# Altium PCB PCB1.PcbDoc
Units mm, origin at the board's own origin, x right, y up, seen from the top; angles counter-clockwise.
Board outline 12.57 x 10.41 mm, 2 copper layers (Top Layer, Bottom Layer); 7 components, 5 nets, 23 pads, 8 vias.
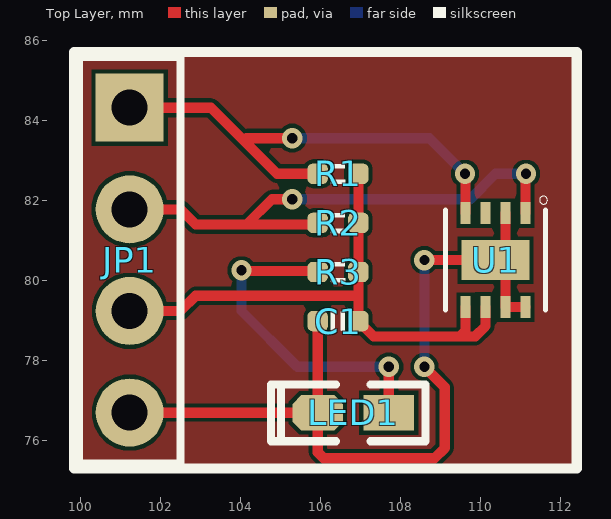
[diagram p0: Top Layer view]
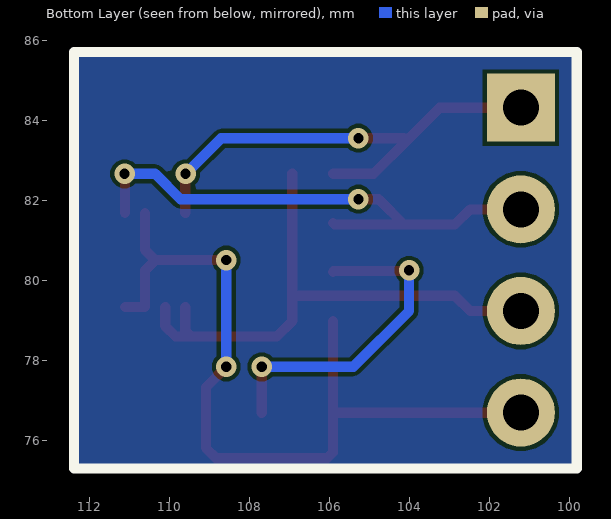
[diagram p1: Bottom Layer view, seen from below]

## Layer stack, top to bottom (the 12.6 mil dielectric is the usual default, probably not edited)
Top Solder: solder mask 0.0102, Solder Resist, Dk 3.5
Top Layer: signal copper 0.0356
Dielectric 1: dielectric 0.32, FR-4, Dk 4.8
Bottom Layer: signal copper 0.0356
Bottom Solder: solder mask 0.0102, Solder Resist, Dk 3.5

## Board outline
99.822,75.311 99.822,85.725 112.395,85.725 112.395,75.311

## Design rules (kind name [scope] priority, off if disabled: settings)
Clearance [All] p1: gap=0.102 ignorepadtopadclearanceinfootprint=FALSE except(0: Arc-Hole Track-Hole SMDPad-Hole THPad-Hole Via-Hole Fill-Hole Poly-Hole Region-Hole Text-Hole; 0.064: SMDPad-Via)
ComponentClearance [All] p1: gap=0 collisioncheckmode=3 verticalgap=0 showdistances=FALSE
DiffPairsRouting [All] p1: maxlimit=0.102 minlimit=0.102 mostfreqgap=0.102 toplayer_minwidth=0.102 toplayer_maxwidth=0.102 toplayer_prefwidth=0.102 bottomlayer_minwidth=0.102 bottomlayer_maxwidth=0.102 bottomlayer_prefwidth=0.102 maxuncoupledlength=12.7
FanoutControl Fanout_BGA [All] p1: bgadir=Out bgaviamode=Centered fanoutstyle=Auto fanoutdirection=Alternating viagrid=0.025 // Fanout_BGA (Default Rule)
HoleSize [All] p1: absolutevalues=TRUE maxlimit=254 minlimit=0.089 maxpercent=80.000 minpercent=20.000
MatchedLengths MatchedLengths_DIFF [InDifferentialPairClass('All Differential Pairs')] p1: tolerance=0.127 checknetsindiffpair=TRUE checkdiffpairvsdiffpair=FALSE checkxsignals=FALSE checkothers=FALSE
MatchedLengths MatchedLengths_DQS1 [InDifferentialPair('SDQS1')] p2: tolerance=0.127 checknetsindiffpair=TRUE checkdiffpairvsdiffpair=FALSE checkxsignals=FALSE checkothers=FALSE
MatchedLengths MatchedLengths_DQS0 [InDifferentialPair('SDQS0')] p3: tolerance=0.127 checknetsindiffpair=TRUE checkdiffpairvsdiffpair=FALSE checkxsignals=FALSE checkothers=FALSE
MatchedLengths MatchedLengths_SCK_CS [InNetClass('DDR_SCK_CS')] p4: tolerance=7.62 checknetsindiffpair=FALSE checkdiffpairvsdiffpair=TRUE checkxsignals=TRUE checkothers=TRUE
MatchedLengths MatchedLengths_SCK_DQS [InNetClass('DDR_SCK_DQS')] p5: tolerance=15.24 checknetsindiffpair=FALSE checkdiffpairvsdiffpair=TRUE checkxsignals=TRUE checkothers=TRUE
MatchedLengths MatchedLengths_CMD [InNetClass('DDR_CMD')] p6: tolerance=12.7 checknetsindiffpair=FALSE checkdiffpairvsdiffpair=TRUE checkxsignals=TRUE checkothers=TRUE
MatchedLengths MatchedLengths_DATAH [InNetClass('DDR_DATAH')] p7: tolerance=6.35 checknetsindiffpair=FALSE checkdiffpairvsdiffpair=TRUE checkxsignals=TRUE checkothers=TRUE
MatchedLengths MatchedLengths_DATAL [InNetClass('DDR_DATAL')] p8: tolerance=6.35 checknetsindiffpair=FALSE checkdiffpairvsdiffpair=TRUE checkxsignals=TRUE checkothers=TRUE
MatchedLengths MatchedLengths_SCK [InDifferentialPair('SCK')] p9: tolerance=0.127 checknetsindiffpair=TRUE checkdiffpairvsdiffpair=FALSE checkxsignals=FALSE checkothers=FALSE
MinimumSolderMaskSliver [All] p1 off: minsoldermaskwidth=0.051
PlaneClearance [All] p1: clearance=0.203
PlaneConnect [All] p1: planeconnectstyle=Direct reliefexpansion=0.508 reliefentries=4 reliefconductorwidth=0.254 reliefairgap=0.254
PolygonConnect PolygonConnect_VDD-5V [All vs IsNamedPolygon('VDD-5V_L01_P009')] p1: thpad.connectstyle=Direct thpad.reliefconductorwidth=0.254 thpad.reliefentries=4 thpad.polygonreliefangle="90 Angle" thpad.airgapwidth=0.254 smdpad.connectstyle=Relief smdpad.reliefconductorwidth=0.254 smdpad.reliefentries=4 smdpad.polygonreliefangle="90 Angle" smdpad.airgapwidth=0.254 via.connectstyle=Direct via.reliefconductorwidth=0.254 via.reliefentries=4 via.polygonreliefangle="90 Angle" via.airgapwidth=0.254
PolygonConnect [All] p2: connectstyle=Direct reliefconductorwidth=0.254 reliefentries=4 polygonreliefangle="90 Angle" airgapwidth=0.254
RoutingVias [All] p1: holewidth=0.203 width=0.406 viastyle="Through Hole" minholewidth=0.152 minwidth=0.305 maxholewidth=0.711 maxwidth=1.27
SilkToSilkClearance [All] p1: silktosilkclearance=0
SilkToSolderMaskClearance [IsPad] p1: minsilkscreentomaskgap=0 clearancetoexposedcopper=TRUE
SolderMaskExpansion [All] p1: expansion=0.076 istentingtop=FALSE
Width GND [(InNet('AGND') OR InNet('GND'))] p1: maxlimit=1.27 minlimit=0.102 preferedwidth=0.254
Width VCC [(InNet('VDD_SYS_3.3V') OR InNet('VDD_AV_3.3V') OR InNet('VDD_5V') OR InNet('VDD1V2-SYS') OR InNet('VDD1V1-EPHY') OR InNet('VDD-CPUX') OR InNet('VDD-CPUS') OR InNet('VDD-CPUFB') OR InNet('VCC-DRAM'))] p2: maxlimit=1.27 minlimit=0.102 preferedwidth=0.254
Width [All] p3: maxlimit=254 minlimit=0.102 preferedwidth=0.102
21 further rules are at their usual default settings.

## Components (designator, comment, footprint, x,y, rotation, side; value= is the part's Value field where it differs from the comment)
C1 "0.1uF" CAP_0402 106.426,78.994 r180 top value=0.1u
JP1 "HDR-1X4" HDR2.54-LI-4P 101.219,80.518 r270 top
LED1 "红色" LED0603_R 106.807,76.708 r180 top
R1 "10K" RES_0402 106.426,82.677 r0 top value=22R
R2 "10K" RES_0402 106.426,81.449 r0 top value=22R
R3 "10K" RES_0402 106.426,80.222 r0 top value=22R
U1 "SHT30-DIS" DFN250X250X100-9N 110.363,80.518 r270 top locked

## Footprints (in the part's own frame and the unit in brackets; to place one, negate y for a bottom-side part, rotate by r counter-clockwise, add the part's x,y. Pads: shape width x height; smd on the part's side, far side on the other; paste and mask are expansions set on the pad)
CAP_0402 [mil]
  rrect50% 20x20 smd: 1(-20,0) 2(20,0)
  silkscreen extent -7,-9 7,9, body extent -20,-10 20,10, height 20
DFN250X250X100-9N [mm]
  rect 0.55x0.25 smd: 1(-1.175,0.75) 2(-1.175,0.25) 3(-1.175,-0.25) 4(-1.175,-0.75) 5(1.175,-0.75) 6(1.175,-0.25) 7(1.175,0.25) 8(1.175,0.75)
  rect 1x1.7 smd: 9(0,0)
  silkscreen extent -1.6,-1.25 1.25,1.3, body extent -1.25,-1.25 1.25,1.25, height 0.9
HDR2.54-LI-4P [mm] "排针，4脚"
  rect 1.7x1.7 hole 0.9: 1(-3.81,0)
  round 1.7 hole 0.9: 2(-1.27,0) 3(1.27,0) 4(3.81,0)
  silkscreen extent -5.08,-1.27 5.08,1.27, body extent -5.08,-1.27 5.08,1.27, height 2.54
LED0603_R [mil] "红色0603LED"
  rect 50x35 smd: 1(-35,0.26)
  oct 50x35 smd: 2(35,0.26)
  silkscreen extent -71,-28 81,28, body extent -32,-16 31,16, height 18
RES_0402 [mil]
  rrect50% 20x20 smd: 1(-20,0) 2(20,0)
  silkscreen extent -6,-10 6,10, body extent -20,-10 20,10, height 14

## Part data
C1: library part 电容-0402, "Capacitor"
JP1: library part "Header 4", "4P接插件"
LED1: library part LED-SMD, "贴片LED"
R1 R2 R3: library part 电阻-0402, "Resistor"
U1: "SHT3x Series 5.5 V 卤3 %RH 0 to 100% Temperature and Humidity Sensor - DFN-8", Package=None

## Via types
v1: diameter 0.508, hole 0.254, Top Layer to Bottom Layer, tented both sides, 8 vias

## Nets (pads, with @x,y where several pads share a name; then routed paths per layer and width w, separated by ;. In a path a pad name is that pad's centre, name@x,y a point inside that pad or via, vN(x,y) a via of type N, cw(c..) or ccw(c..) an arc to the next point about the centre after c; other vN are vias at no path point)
GND: C1.2 JP1.4 LED1.2 U1.2 U1.7 U1.8 U1.9 | length 21.1
  Top Layer w0.254: JP1.4 101.222,76.705 105.915,76.705 LED1.2 ; C1.2 LED1.2 ; v1(108.585,77.851) 109.093,77.343 109.093,75.819 108.839,75.565 106.067,75.565 105.918,75.714 LED1.2 ; v1(108.585,80.518) U1.9 ; U1.2 110.613,80.768 U1.9 ; U1.8 U1.7 110.613,80.268 U1.9
  Bottom Layer w0.254: v1(108.585,77.851) v1(108.585,80.518)
NetLED1_1: LED1.1 R3.1 | length 8.3
  Top Layer w0.254: v1(104.013,80.264) 104.034,80.243 105.897,80.243 R3.1 ; LED1.1 v1(107.696,77.851)
  Bottom Layer w0.254: v1(104.013,80.264) 104.013,79.248 105.41,77.851 v1(107.696,77.851)
SCL: JP1.1 R1.1 U1.4 | length 12.3
  Top Layer w0.254: JP1.1 103.251,84.328 104.077,83.502 ; v1(105.283,83.566) 104.14,83.566 104.077,83.502 ; R1.1 104.902,82.677 104.077,83.502 ; v1(109.601,82.677) 109.611,82.667 109.611,81.695 U1.4
  Bottom Layer w0.254: v1(105.283,83.566) 108.712,83.566 v1(109.601,82.677)
SDA: JP1.2 R2.1 U1.1 | length 13.4
  Top Layer w0.254: JP1.2 102.489,81.788 102.87,81.407 104.14,81.407 ; v1(105.283,82.042) 104.775,82.042 104.14,81.407 ; R2.1 105.876,81.407 104.14,81.407 ; U1.1 111.115,81.695 111.115,82.667 v1(111.125,82.677)
  Bottom Layer w0.254: v1(105.283,82.042) 109.728,82.042 110.363,82.677 v1(111.125,82.677)
VCC: C1.1 JP1.3 R1.2 R2.2 R3.2 U1.5 U1.6 | length 14.3
  Top Layer w0.254: JP1.3 102.489,79.248 102.87,79.629 106.913,79.629 106.934,79.608 ; R1.2 R2.2 R3.2 106.934,79.608 ; U1.5 109.611,79.341 109.611,78.75 109.474,78.613 ; U1.6 110.111,79.341 110.111,78.869 109.855,78.613 109.474,78.613 ; 106.934,79.608 C1.1 107.315,78.613 109.474,78.613
pads on no net: U1.3

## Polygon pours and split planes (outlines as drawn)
no net on Top Layer "NONET_L01_P001" (solid, pour order 1): 99.822,85.725 112.395,85.725 112.395,75.311 99.822,75.311
no net on Bottom Layer "NONET_L02_P002" (solid, pour order 2): 99.822,85.725 112.395,85.725 112.395,75.311 99.822,75.311

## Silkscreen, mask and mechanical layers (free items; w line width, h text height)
Top Overlay:
  the board outline again, w0.254
Bottom Overlay:
  the board outline again, w0.254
